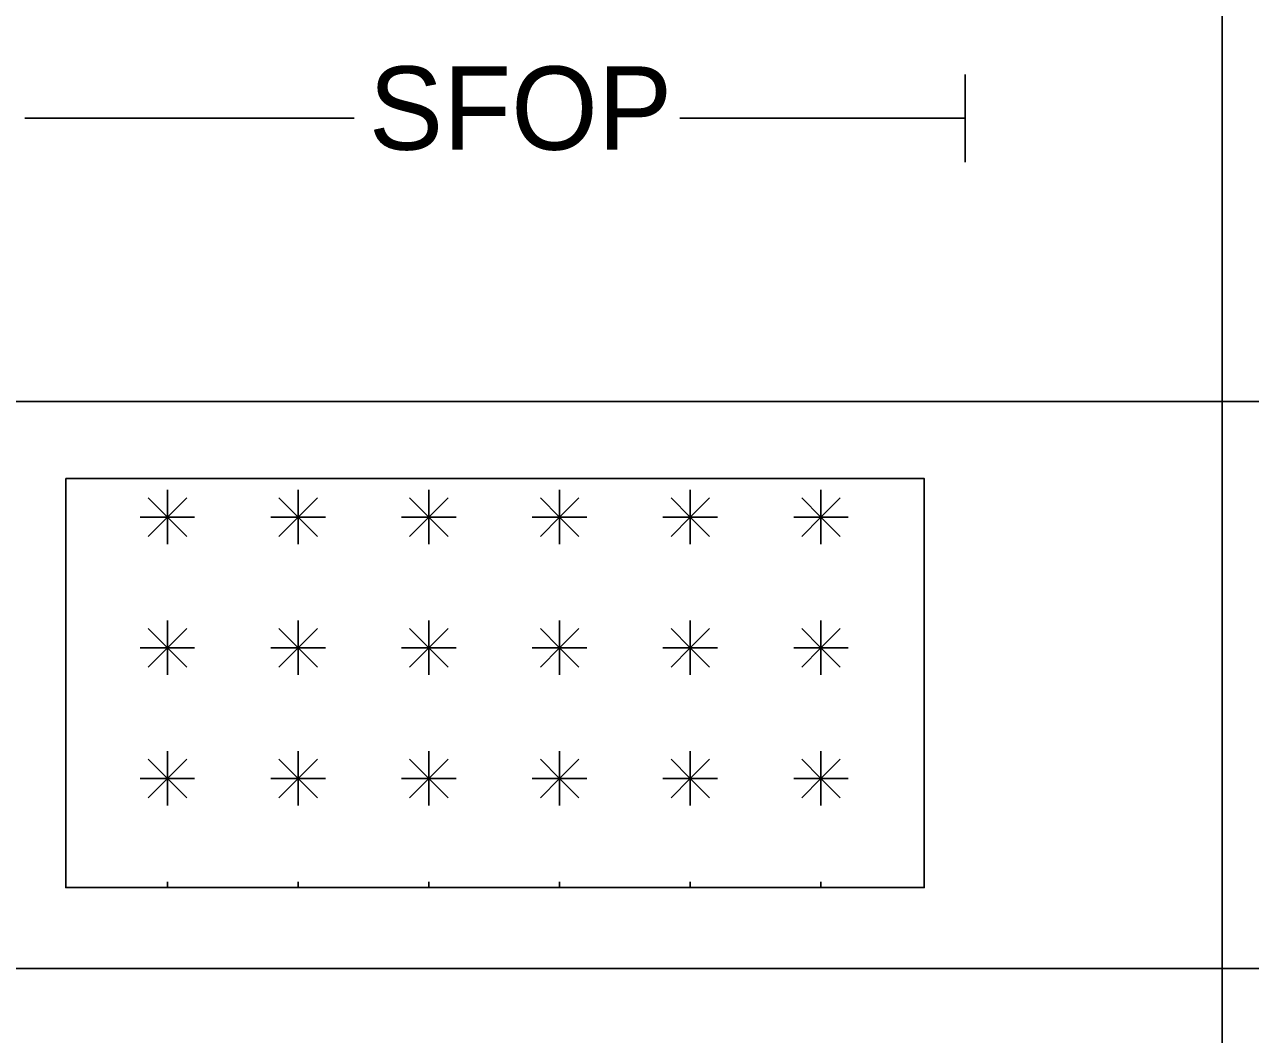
# Model space of a CAD drawing. Extents: x 1.3 to 34, y 0 to 22.5.
# Drawn here: x 11.694 to 12.775, y 8.767 to 9.657 of the extents above; entities that cross this region are included whole.
import ezdxf

# ---------------------------------------------------------------- set-up
doc = ezdxf.new("R2010")
doc.units = 0
for name, color, linetype in [('ANNO-SYMB', 7, 'Continuous'), ('ANNO-TABL', 7, 'Continuous'), ('USER-LINE', 7, 'Continuous')]:
    doc.layers.add(name, color=color, linetype=linetype)

msp = doc.modelspace()

# ---------------------------------------------------------------- linework, layer by layer
at = {"layer": 'ANNO-SYMB'}
for p, q in [((12.5236, 9.5746), (12.5236, 9.6132)), ((11.6948, 9.5746), (11.985, 9.5746)), ((12.2719, 9.5746), (12.5242, 9.5746)), ((12.5236, 9.536), (12.5236, 9.5746)), ((11.8204, 9.223), (11.8035, 9.2399)), ((11.8204, 9.223), (11.8204, 9.247)), ((11.8204, 9.223), (11.8204, 9.247)), ((11.8204, 9.223), (11.8374, 9.2399)), ((11.9356, 9.223), (11.9187, 9.2399)), ((11.9356, 9.247), (11.9356, 9.223)), ((11.9356, 9.223), (11.9526, 9.2399)), ((12.0508, 9.223), (12.0339, 9.2399)), ((12.0508, 9.223), (12.0508, 9.247)), ((12.0508, 9.223), (12.0508, 9.247)), ((12.0508, 9.223), (12.0678, 9.2399)), ((12.166, 9.223), (12.1491, 9.2399)), ((12.166, 9.247), (12.166, 9.223)), ((12.166, 9.223), (12.183, 9.2399)), ((12.2812, 9.223), (12.2643, 9.2399)), ((12.2812, 9.223), (12.2812, 9.247)), ((12.2812, 9.223), (12.2812, 9.247)), ((12.2812, 9.223), (12.2982, 9.2399)), ((12.3964, 9.223), (12.3795, 9.2399)), ((12.3964, 9.247), (12.3964, 9.223)), ((12.3964, 9.223), (12.4134, 9.2399)), ((11.8204, 9.223), (11.7964, 9.223)), ((11.8204, 9.223), (11.8035, 9.206)), ((11.8204, 9.223), (11.8204, 9.199)), ((11.8204, 9.223), (11.8444, 9.223)), ((11.8204, 9.223), (11.8204, 9.199)), ((11.8204, 9.223), (11.8374, 9.206)), ((11.9116, 9.223), (11.9356, 9.223)), ((11.9356, 9.223), (11.9187, 9.206)), ((11.9356, 9.223), (11.9356, 9.199)), ((11.9356, 9.223), (11.9596, 9.223)), ((11.9356, 9.223), (11.9526, 9.206)), ((12.0508, 9.223), (12.0268, 9.223)), ((12.0508, 9.223), (12.0339, 9.206)), ((12.0508, 9.223), (12.0508, 9.199)), ((12.0508, 9.223), (12.0748, 9.223)), ((12.0508, 9.223), (12.0508, 9.199)), ((12.0508, 9.223), (12.0678, 9.206)), ((12.142, 9.223), (12.166, 9.223)), ((12.166, 9.223), (12.1491, 9.206)), ((12.166, 9.223), (12.166, 9.199)), ((12.166, 9.223), (12.19, 9.223)), ((12.166, 9.223), (12.183, 9.206)), ((12.2812, 9.223), (12.2572, 9.223)), ((12.2812, 9.223), (12.2643, 9.206)), ((12.2812, 9.223), (12.2812, 9.199)), ((12.2812, 9.223), (12.3052, 9.223)), ((12.2812, 9.223), (12.2812, 9.199)), ((12.2812, 9.223), (12.2982, 9.206)), ((12.3724, 9.223), (12.3964, 9.223)), ((12.3964, 9.223), (12.3795, 9.206)), ((12.3964, 9.223), (12.3964, 9.199)), ((12.3964, 9.223), (12.4204, 9.223)), ((12.3964, 9.223), (12.4134, 9.206)), ((11.8204, 9.1078), (11.8204, 9.1318)), ((11.8204, 9.1078), (11.8204, 9.1318)), ((11.9356, 9.1078), (11.9356, 9.1318)), ((12.0508, 9.1078), (12.0508, 9.1318)), ((12.0508, 9.1078), (12.0508, 9.1318)), ((12.166, 9.1078), (12.166, 9.1318)), ((12.2812, 9.1078), (12.2812, 9.1318)), ((12.2812, 9.1078), (12.2812, 9.1318)), ((12.3964, 9.1078), (12.3964, 9.1318)), ((11.8204, 9.1078), (11.8035, 9.1247)), ((11.8204, 9.1078), (11.8374, 9.1247)), ((11.9356, 9.1078), (11.9187, 9.1247)), ((11.9356, 9.1078), (11.9526, 9.1247)), ((12.0508, 9.1078), (12.0339, 9.1247)), ((12.0508, 9.1078), (12.0678, 9.1247)), ((12.166, 9.1078), (12.1491, 9.1247)), ((12.166, 9.1078), (12.183, 9.1247)), ((12.2812, 9.1078), (12.2643, 9.1247)), ((12.2812, 9.1078), (12.2982, 9.1247)), ((12.3964, 9.1078), (12.3795, 9.1247)), ((12.3964, 9.1078), (12.4134, 9.1247)), ((11.8204, 9.1078), (11.7964, 9.1078)), ((11.8204, 9.1078), (11.7964, 9.1078)), ((11.8204, 9.1078), (11.8035, 9.0908)), ((11.8204, 9.1078), (11.8204, 9.0838)), ((11.8204, 9.1078), (11.8374, 9.0908)), ((11.8204, 9.1078), (11.8204, 9.0838)), ((11.8204, 9.1078), (11.8444, 9.1078)), ((11.8204, 9.1078), (11.8444, 9.1078)), ((11.9356, 9.1078), (11.9116, 9.1078)), ((11.9356, 9.1078), (11.9116, 9.1078)), ((11.9356, 9.1078), (11.9187, 9.0908)), ((11.9356, 9.1078), (11.9356, 9.0838)), ((11.9356, 9.1078), (11.9596, 9.1078)), ((11.9356, 9.1078), (11.9526, 9.0908)), ((11.9356, 9.1078), (11.9596, 9.1078)), ((12.0508, 9.1078), (12.0268, 9.1078)), ((12.0508, 9.1078), (12.0268, 9.1078)), ((12.0508, 9.1078), (12.0339, 9.0908)), ((12.0508, 9.1078), (12.0508, 9.0838)), ((12.0508, 9.1078), (12.0678, 9.0908)), ((12.0508, 9.1078), (12.0508, 9.0838)), ((12.0508, 9.1078), (12.0748, 9.1078)), ((12.0508, 9.1078), (12.0748, 9.1078)), ((12.166, 9.1078), (12.142, 9.1078)), ((12.166, 9.1078), (12.142, 9.1078)), ((12.166, 9.1078), (12.1491, 9.0908)), ((12.166, 9.1078), (12.166, 9.0838)), ((12.166, 9.1078), (12.19, 9.1078)), ((12.166, 9.1078), (12.183, 9.0908)), ((12.166, 9.1078), (12.19, 9.1078)), ((12.2812, 9.1078), (12.2572, 9.1078)), ((12.2812, 9.1078), (12.2572, 9.1078)), ((12.2812, 9.1078), (12.2643, 9.0908)), ((12.2812, 9.1078), (12.2812, 9.0838)), ((12.2812, 9.1078), (12.2982, 9.0908)), ((12.2812, 9.1078), (12.2812, 9.0838)), ((12.2812, 9.1078), (12.3052, 9.1078)), ((12.2812, 9.1078), (12.3052, 9.1078)), ((12.3964, 9.1078), (12.3724, 9.1078)), ((12.3964, 9.1078), (12.3724, 9.1078)), ((12.3964, 9.1078), (12.3795, 9.0908)), ((12.3964, 9.1078), (12.3964, 9.0838)), ((12.3964, 9.1078), (12.4204, 9.1078)), ((12.3964, 9.1078), (12.4134, 9.0908)), ((12.3964, 9.1078), (12.4204, 9.1078)), ((11.8204, 8.9926), (11.8204, 9.0166)), ((11.8204, 8.9926), (11.8204, 9.0166)), ((11.9356, 9.0166), (11.9356, 8.9926)), ((12.0508, 8.9926), (12.0508, 9.0166)), ((12.0508, 8.9926), (12.0508, 9.0166)), ((12.166, 9.0166), (12.166, 8.9926)), ((12.2812, 8.9926), (12.2812, 9.0166)), ((12.2812, 8.9926), (12.2812, 9.0166)), ((12.3964, 9.0166), (12.3964, 8.9926)), ((11.8204, 8.9926), (11.8035, 9.0095)), ((11.8204, 8.9926), (11.8374, 9.0095)), ((11.9356, 8.9926), (11.9187, 9.0095)), ((11.9356, 8.9926), (11.9526, 9.0095)), ((12.0508, 8.9926), (12.0339, 9.0095)), ((12.0508, 8.9926), (12.0678, 9.0095)), ((12.166, 8.9926), (12.1491, 9.0095)), ((12.166, 8.9926), (12.183, 9.0095)), ((12.2812, 8.9926), (12.2643, 9.0095)), ((12.2812, 8.9926), (12.2982, 9.0095)), ((12.3964, 8.9926), (12.3795, 9.0095)), ((12.3964, 8.9926), (12.4134, 9.0095)), ((11.8204, 8.9926), (11.7964, 8.9926)), ((11.8204, 8.9926), (11.8035, 8.9756)), ((11.8204, 8.9926), (11.8204, 8.9686)), ((11.8204, 8.9926), (11.8444, 8.9926)), ((11.8204, 8.9926), (11.8204, 8.9686)), ((11.8204, 8.9926), (11.8374, 8.9756)), ((11.9116, 8.9926), (11.9356, 8.9926)), ((11.9356, 8.9926), (11.9187, 8.9756)), ((11.9356, 8.9926), (11.9356, 8.9686)), ((11.9356, 8.9926), (11.9596, 8.9926)), ((11.9356, 8.9926), (11.9526, 8.9756)), ((12.0508, 8.9926), (12.0268, 8.9926)), ((12.0508, 8.9926), (12.0339, 8.9756)), ((12.0508, 8.9926), (12.0508, 8.9686)), ((12.0508, 8.9926), (12.0748, 8.9926)), ((12.0508, 8.9926), (12.0508, 8.9686)), ((12.0508, 8.9926), (12.0678, 8.9756)), ((12.142, 8.9926), (12.166, 8.9926)), ((12.166, 8.9926), (12.1491, 8.9756)), ((12.166, 8.9926), (12.166, 8.9686)), ((12.166, 8.9926), (12.19, 8.9926)), ((12.166, 8.9926), (12.183, 8.9756)), ((12.2812, 8.9926), (12.2572, 8.9926)), ((12.2812, 8.9926), (12.2643, 8.9756)), ((12.2812, 8.9926), (12.2812, 8.9686)), ((12.2812, 8.9926), (12.3052, 8.9926)), ((12.2812, 8.9926), (12.2812, 8.9686)), ((12.2812, 8.9926), (12.2982, 8.9756)), ((12.3724, 8.9926), (12.3964, 8.9926)), ((12.3964, 8.9926), (12.3795, 8.9756)), ((12.3964, 8.9926), (12.3964, 8.9686)), ((12.3964, 8.9926), (12.4204, 8.9926)), ((12.3964, 8.9926), (12.4134, 8.9756)), ((11.8204, 8.8964), (11.8204, 8.9014)), ((11.8204, 8.8964), (11.8204, 8.9014)), ((11.9356, 8.8964), (11.9356, 8.9014)), ((12.0508, 8.8964), (12.0508, 8.9014)), ((12.0508, 8.8964), (12.0508, 8.9014)), ((12.166, 8.8964), (12.166, 8.9014)), ((12.2812, 8.8964), (12.2812, 8.9014)), ((12.2812, 8.8964), (12.2812, 8.9014)), ((12.3964, 8.8964), (12.3964, 8.9014))]:
    msp.add_line(p, q, dxfattribs=at)
msp.add_lwpolyline([(11.7308, 9.2569), (12.4875, 9.2569), (12.4875, 8.8964), (11.7308, 8.8964)], close=True, dxfattribs=at)
at = {"layer": 'ANNO-TABL'}
for p, q in [((2, 9.325), (18.2, 9.325)), ((2, 8.825), (18.2, 8.825))]:
    msp.add_line(p, q, dxfattribs=at)
at = {"layer": 'USER-LINE'}
for p, q in [((12.75, 9.325), (12.75, 9.825)), ((12.75, 9.325), (11.4, 9.325)), ((12.75, 8.825), (12.75, 9.325)), ((12.75, 8.825), (11.4, 8.825)), ((12.75, 8.325), (12.75, 8.825))]:
    msp.add_line(p, q, dxfattribs=at)

# ---------------------------------------------------------------- texts
at = {"layer": 'ANNO-SYMB'}
msp.add_text('SFOP', height=0.07344, dxfattribs=at).set_placement((11.9979, 9.5469))

doc.saveas('drawing.dxf')
